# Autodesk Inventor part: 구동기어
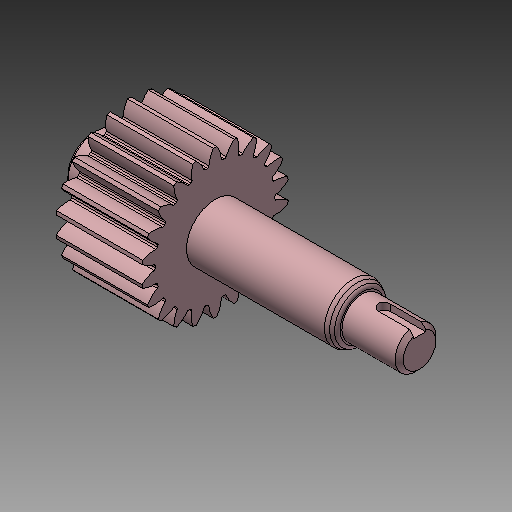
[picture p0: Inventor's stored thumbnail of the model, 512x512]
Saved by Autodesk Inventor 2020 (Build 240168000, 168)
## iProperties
Created: 2024-02
Part Number: 구동기어
Material: 강철, 탄소
Document SubType Name: Modeling
Designer: mdu-01
Density: 1 g/cm^3
Appearance: 기본값(1)
Author: mdu-01
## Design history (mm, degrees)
sketch "스케치1"
  geometry: L1 (0, 0)-(80, 0); L2 (80, 0)-(80, 4); L3 (79, 5)-(66, 5); L4 (66, 5)-(66, 5.423); L5 (63.732, 7)-(30, 7); L6 (30, 7)-(30, 14.625); L7 (30, 14.625)-(9, 14.625); L8 (9, 14.625)-(9, 7); L9 (9, 7)-(1, 7); L10 (0, 6)-(0, 0); L11 (9, 16.5)-(30, 16.5); L12 (80, 4)-(79, 5); L13 (1, 7)-(0, 6); L14 (65.5, 6.289)-(64.732, 6.732); L15 (70, 5)-(70, 3.2); L16 (70, 3.2)-(80, 3.2); A1 r 2 centre (63.732, 5) between (64.732, 6.732) and (63.732, 7); A2 r 1 centre (65, 5.423) between (66, 5.423) and (65.5, 6.289); 3 further points
  constraints: 32 end point, 10 point on line, 8 parallel, 4 perpendicular, 4 point on circle, 4 tangent, 2 centre point, 1 collinear, 1 horizontal
  dimensions: "d0" = 14 diameter of L9 L1; "d2" = 9 distance between parallel lines of L8 L10; "d3" = 21 distance between parallel lines of L6 L8; "d4" = 33 diameter of L11 L1; "d5" = 1.875 distance between parallel lines of L7 L11; "d6" = 14 distance between parallel lines of L2 L4; "d7" = 50 distance between parallel lines of L6 L2; "d8" = 10 diameter of L3 L1; "d9" = 1 distance of L2.end point (80, 5); "d10" = 1 distance of L3.start point (80, 5) (= d9); "d11" = 1 distance of L9.end point (0, 7) (= d9); "d12" = 1 distance of L10.start point (0, 7) (= d11); "d13" = 12 diameter of point (66, 6) L1; "d14" = 30 deg angle of L5 L14; "d15" = 2 radius of A1; "d16" = 1 radius of A2; "d17" = 1.8 distance between parallel lines of L16 L3; "d18" = 10 distance between parallel lines of L15 L2
revolve "회전1" stored, may be unused: angle "d19" = 90 deg
extrude "돌출1" cut sketch "스케치1" stored distance "d20" = 3; taper "d21" = 0 deg
fillet "모깎기1"
sketch "스케치2" dims "d22" = 33
  geometry: L1 (0, 0)-(0, 18); A1 r 18 centre (0, 0) between (0.428, 17.995) and (-0.428, 17.995); A2 r 7.045 centre (-5.482, 14.16) between (1.553, 14.542) and (0.428, 17.995); A3 r 7.045 centre (5.482, 14.16) between (-0.428, 17.995) and (-1.553, 14.542); A4 r 14.625 centre (0, 0) between (1.553, 14.542) and (-1.553, 14.542); 3 further points
  constraints: 10 point on circle, 4 centre point, 3 symmetric about line, 2 coincident, 2 end point, 1 vertical, 8 other
  dimensions: "d23" = 1.5 dimension on A1; "d24" = 1.1775 horizontal distance of point (1.178, 16.458) point (0, 0); "d25" = 0.75 horizontal distance of A1.start point (1.178, 16.458); "d26" = 0.375 horizontal distance of A2.start point (1.178, 16.458)
extrude "돌출2" join sketch "스케치2" stored distance "d27" = 3; taper "d28" = 0 deg
fillet "모깎기2" dims "d32" = 0.375
node "솔리드1"
pattern_circular "원형 패턴1" dims angle "d34" = 360 deg
